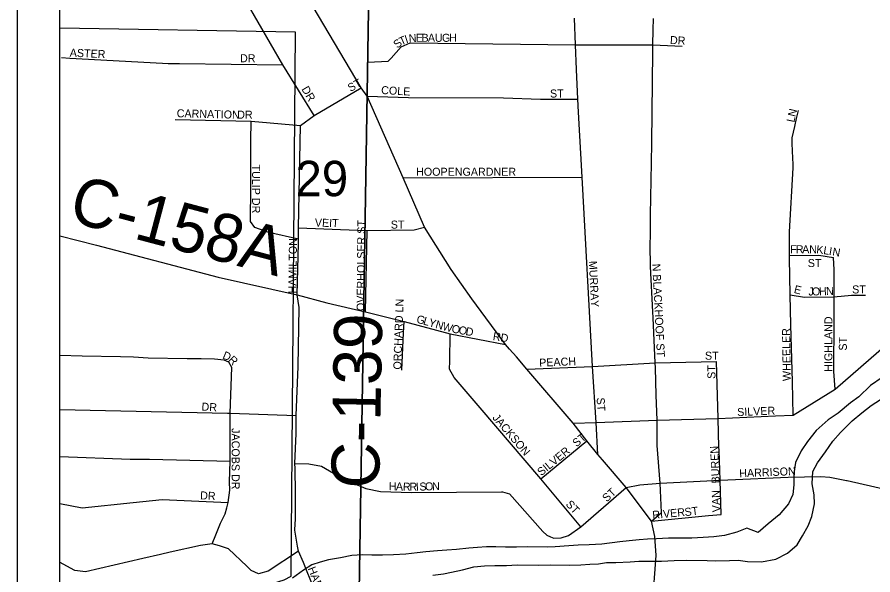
# Model space of a CAD drawing. Extents: x -784 to 1375, y -225 to 440.
# Drawn here: x 65.09 to 105.18, y 360.96 to 387.07 of the extents above; entities that cross this region are included whole.
import ezdxf

# ---------------------------------------------------------------- set-up
doc = ezdxf.new("R2010")
doc.units = 0
for name, color, linetype in [('GM_X_City_Street', 7, 'Continuous'), ('GM_X_City_Street_Text', 7, 'Continuous'), ('GM_X_County_Road', 7, 'Continuous'), ('GM_X_County_Road_Text', 7, 'Continuous'), ('GM_X_Major_River', 7, 'Continuous'), ('GM_X_Section', 7, 'Continuous'), ('GM_X_Section_Text', 7, 'Continuous'), ('GM_X_State_Route', 7, 'Continuous'), ('GM_X_Township_Subdivision', 7, 'Continuous'), ('GM_X_Township_Subdivision_Text', 7, 'Continuous'), ('SH_Data', 7, 'Continuous'), ('SH_Text', 7, 'Continuous')]:
    doc.layers.add(name, color=color, linetype=linetype)

msp = doc.modelspace()

# ---------------------------------------------------------------- linework, layer by layer
at = {"layer": 'GM_X_City_Street'}
for points in [[(78.997, 382.464), (77.542, 384.845), (75.795, 387.841), (74.481, 389.954), (73.204, 392.102)], [(91.299, 384.626), (91.251, 385.781), (91.193, 387.031)], [(94.867, 385.449), (94.871, 385.773), (94.887, 386.476), (94.895, 387.007)], [(82.604, 385.151), (83.079, 385.683), (83.496, 385.863), (91.251, 385.781), (94.871, 385.773), (96.249, 385.72)], [(94.762, 376.883), (94.764, 376.956), (94.756, 377.822), (94.813, 380.249), (94.821, 381.181), (94.867, 385.449)], [(67.166, 385.177), (67.561, 385.156), (71.899, 384.924), (72.172, 384.909), (72.688, 384.897), (77.542, 384.845)], [(81.51, 384.972), (82.474, 385.005), (82.604, 385.151)], [(91.391, 382.621), (91.357, 383.237), (91.299, 384.626)], [(78.263, 376.49), (78.268, 376.681), (78.276, 377.205), (78.366, 381.996), (78.997, 382.464), (81.206, 383.768)], [(81.494, 383.378), (83.422, 383.313), (87.876, 383.289), (89.603, 383.236), (89.623, 383.236), (91.357, 383.237)], [(92.295, 366.592), (92.218, 368.088), (92.035, 370.713), (91.561, 379.579), (91.391, 382.621)], [(101.271, 375.784), (101.269, 375.918), (101.277, 377.029), (101.444, 380.013), (101.439, 380.178), (101.416, 380.791), (101.402, 381.18), (101.393, 381.425), (101.515, 381.945), (101.603, 382.324), (101.692, 382.703)], [(72.489, 382.279), (76.053, 382.201), (78.366, 381.996)], [(78.268, 376.681), (76.884, 376.988), (76.22, 377.231), (76.015, 377.499), (76.015, 378.112), (76.041, 378.508), (76.041, 381.281), (76.053, 382.201)], [(83.168, 379.55), (91.561, 379.579)], [(81.035, 377.095), (81.483, 377.077), (83.693, 377.116), (84.172, 377.245)], [(78.276, 377.205), (81.035, 377.095)], [(81.407, 373.283), (81.483, 377.077)], [(94.877, 372.992), (94.862, 373.278), (94.764, 375.403), (94.748, 376.417), (94.762, 376.883)], [(78.2, 374.075), (78.263, 376.49)], [(101.269, 375.918), (102.65, 375.934), (103.328, 375.82)], [(101.44, 368.441), (101.408, 370.002), (101.334, 372.666), (101.301, 374.071), (101.271, 375.784)], [(103.41, 369.658), (103.353, 370.484), (103.369, 372.886), (103.369, 373.973), (103.361, 375.248), (103.328, 375.82)], [(101.301, 374.071), (101.98, 373.957), (103.369, 373.973), (103.506, 373.987)], [(103.506, 373.987), (103.688, 374.006), (104.17, 374.055), (104.832, 374.063)], [(81.407, 373.283), (83.221, 372.823), (85.38, 372.248), (87.965, 371.742)], [(94.99, 370.658), (94.985, 370.884), (94.877, 372.992)], [(83.112, 370.549), (83.183, 372.293), (83.221, 372.823)], [(91.136, 368.057), (92.218, 368.088), (95.074, 368.197), (97.931, 368.286), (100.615, 368.4), (101.44, 368.441), (103.41, 369.658), (107.019, 372.788)], [(86.782, 368.778), (85.565, 370.204), (85.348, 370.587), (85.353, 370.97), (85.38, 372.248)], [(88.97, 370.59), (92.035, 370.713), (94.985, 370.884), (97.853, 370.95)], [(97.969, 366.8), (97.963, 366.933), (97.931, 368.286), (97.853, 370.95)], [(94.813, 363.473), (95.271, 363.881), (95.207, 365.254), (95.075, 367.011), (95.074, 368.197), (95.017, 369.372), (94.99, 370.658)], [(91.496, 363.211), (89.622, 365.451), (86.782, 368.778)], [(89.622, 365.451), (91.773, 367.231)], [(98.074, 363.783), (98.025, 365.397), (97.969, 366.8)], [(78.102, 366.17), (78.75, 366.163), (79.34, 366.049), (80.388, 365.444), (81.431, 365.011), (82.118, 364.87), (83.565, 364.817), (87.78, 364.844)], [(93.612, 365.05), (94.258, 365.172), (95.207, 365.254), (98.025, 365.397), (98.38, 365.412)], [(98.38, 365.412), (101.212, 365.528), (102.74, 365.569), (103.165, 365.536), (103.944, 365.378)], [(103.944, 365.378), (103.973, 365.372), (106.368, 364.833), (107.061, 364.692)], [(87.78, 364.844), (87.82, 364.844), (88.152, 364.748), (89.718, 362.985), (89.903, 362.819), (90.08, 362.743)], [(90.08, 362.743), (90.229, 362.679), (90.58, 362.698), (90.912, 362.8), (91.496, 363.211), (93.612, 365.05)], [(94.813, 363.473), (97.469, 363.734), (98.074, 363.783)], [(80.763, 356.122), (80.35, 357.171), (79.837, 358.365), (79.646, 358.801), (79.202, 359.826), (78.949, 360.416), (78.674, 361.097), (78.505, 361.533), (78.268, 362.069), (78.228, 362.302)]]:
    msp.add_lwpolyline(points, dxfattribs=at)
at = {"layer": 'GM_X_County_Road'}
for points in [[(67.088, 376.839), (68.806, 376.391), (74.51, 374.895), (78.2, 374.075)], [(78.101, 363.077), (78.123, 363.584), (78.13, 364.273), (78.133, 364.808), (78.108, 365.934), (78.102, 366.17), (78.153, 367.579), (78.153, 368.421), (78.251, 370.723), (78.305, 373.484), (78.2, 374.075)], [(78.2, 374.075), (78.2, 374.075), (79.592, 373.704), (81.407, 373.283)], [(78.228, 362.302), (78.1, 363.048), (78.101, 363.077)]]:
    msp.add_lwpolyline(points, dxfattribs=at)
at = {"layer": 'GM_X_Major_River'}
for points in [[(105.617, 370.205), (105.071, 369.822), (104.524, 369.304), (104.129, 369.009), (103.552, 368.536), (103.082, 368.212), (102.52, 367.724), (102.107, 367.204), (101.816, 366.772), (101.553, 366.22), (101.471, 365.71), (101.479, 365.169), (101.428, 364.719), (101.227, 364.287), (100.785, 363.767), (100.268, 363.353), (99.797, 362.939), (99.274, 363.142), (98.806, 362.953), (98.218, 362.811), (97.722, 362.742), (97.225, 362.704), (96.699, 362.681), (96.128, 362.674), (95.603, 362.681), (95.046, 362.644), (94.626, 362.634), (94.235, 362.595), (93.753, 362.556), (93.317, 362.502), (92.474, 362.394), (91.888, 362.372), (91.377, 362.349), (90.926, 362.325), (90.295, 362.273), (89.919, 362.263), (89.003, 362.276), (88.477, 362.253), (87.966, 362.26), (87.515, 362.266), (87.08, 362.272), (86.659, 362.248), (86.253, 362.209), (85.666, 362.142), (85.215, 362.118), (84.779, 362.094), (84.238, 362.041), (83.831, 361.987), (83.29, 361.934)], [(84.569, 360.94), (85.065, 361.008), (85.442, 361.093), (85.954, 361.191), (86.482, 361.334), (86.978, 361.387), (87.474, 361.396), (88.015, 361.403), (88.511, 361.426), (89.502, 361.413), (90.058, 361.435), (90.974, 361.423), (91.5, 361.43), (91.921, 361.455), (92.327, 361.479), (92.703, 361.534), (93.139, 361.543), (93.8, 361.564), (94.206, 361.604), (94.837, 361.61), (95.273, 361.604), (95.874, 361.641), (96.43, 361.648), (97.421, 361.635), (97.797, 361.614), (98.458, 361.635), (98.864, 361.645), (99.299, 361.594), (99.959, 361.57), (100.637, 361.696), (101.181, 361.974), (101.637, 362.373), (101.883, 362.79), (102.145, 363.252), (102.316, 363.701), (102.444, 364.285), (102.419, 364.706), (102.336, 365.218), (102.359, 365.803), (102.575, 366.206), (102.957, 366.726), (103.294, 367.218), (103.66, 367.633), (104.208, 368.166), (104.664, 368.551), (105.089, 368.89), (105.528, 369.17)], [(83.29, 361.934), (82.719, 361.897), (82.208, 361.889), (81.712, 361.881), (81.262, 361.902), (80.765, 361.864), (80.238, 361.766), (79.681, 361.668), (79.289, 361.553), (78.897, 361.424), (78.503, 361.174), (77.987, 360.805)]]:
    msp.add_lwpolyline(points, dxfattribs=at)
at = {"layer": 'GM_X_Section'}
for points in [[(67.088, 397.216), (81.709, 397.114), (81.068, 357.283), (71.441, 357.464), (71.653, 357.594), (72.121, 357.736), (72.758, 358.099), (73.273, 358.374), (73.924, 358.677), (74.439, 358.982), (75.353, 359.701), (76.082, 360.182), (77.094, 360.568), (77.592, 360.724), (77.925, 360.897), (78.122, 386.365), (67.088, 386.554)], [(121.281, 389.014), (120.755, 357.05), (81.068, 357.283), (81.709, 397.114), (86.63, 397.087)]]:
    msp.add_lwpolyline(points, dxfattribs=at)
at = {"layer": 'GM_X_State_Route'}
for points in [[(81.494, 383.378), (81.206, 383.768), (73.671, 396.504), (73.39, 396.974)], [(81.494, 383.378), (81.51, 384.972), (81.682, 396.541), (81.683, 396.823)], [(88.155, 371.535), (87.965, 371.742), (86.396, 373.891), (85.424, 375.256), (84.172, 377.245), (83.168, 379.55), (81.494, 383.378)], [(92.503, 366.349), (92.295, 366.592), (91.773, 367.231), (91.136, 368.057), (88.97, 370.59), (88.488, 371.17), (88.155, 371.535)], [(94.853, 359.554), (95.026, 361.871), (94.969, 362.762), (94.813, 363.473), (93.612, 365.05), (92.503, 366.349)]]:
    msp.add_lwpolyline(points, dxfattribs=at)
at = {"layer": 'GM_X_Township_Subdivision'}
msp.add_line((67.088, 368.705), (74.937, 368.531), dxfattribs=at)
for points in [[(75.068, 368.528), (75.153, 370.671), (75, 370.916), (74.786, 371.008), (74.327, 371.061), (73.707, 371.077), (73.056, 371.077), (71.235, 371.1), (70.539, 371.146), (69.934, 371.168), (68.128, 371.207), (67.088, 371.238)], [(74.227, 362.413), (74.396, 362.842), (74.618, 363.385), (74.832, 363.814), (74.916, 364.097), (74.977, 364.357), (75.046, 364.924), (75.031, 365.322), (75.062, 366.278), (75.068, 368.528)], [(74.937, 368.531), (75.068, 368.528), (78.153, 368.421)], [(67.088, 366.498), (70.378, 366.385), (71.289, 366.378), (75.062, 366.278)], [(67.088, 364.3), (68.128, 364.097), (70.523, 364.342), (71.878, 364.495), (74.977, 364.357)], [(78.268, 362.069), (76.845, 361.135), (76.401, 361.013), (76.049, 361.166), (75.855, 361.375), (74.993, 362.176), (74.572, 362.322), (74.227, 362.413), (73.684, 362.329), (72.253, 362.031), (71.809, 361.916), (70.983, 361.732), (68.285, 361.109), (67.799, 361.158), (67.245, 361.466)], [(67.245, 361.466), (67.11, 361.541), (67.088, 361.548)]]:
    msp.add_lwpolyline(points, dxfattribs=at)
at = {"layer": 'SH_Data'}
msp.add_line((65.088, 421.485), (65.088, 281.485), dxfattribs=at)
at = {"layer": 'SH_Text'}
msp.add_lwpolyline([(67.088, 419.485), (203.088, 419.485), (203.088, 283.485), (67.088, 283.485)], close=True, dxfattribs=at)

# ---------------------------------------------------------------- texts
at = {"layer": 'GM_X_City_Street_Text'}
for s, rotation, p in [('T', 23.9125, (83.082, 385.744)), ('I', 17.8545, (83.313, 385.847)), ('N', 4.1339, (83.447, 385.893)), ('E', 0.2186, (83.77, 385.917)), ('B', 0, (84.033, 385.918)), ('A', 0, (84.33, 385.918)), ('U', 0, (84.66, 385.918)), ('G', 0, (84.99, 385.918)), ('H', 0, (85.32, 385.918)), ('DR', 356.8222, (95.664, 385.818)), ('S', 38.5318, (82.897, 385.592)), ('ASTER', 357.4519, (67.548, 385.225)), ('DR', 0, (75.53, 384.96)), ('ST', 29.755, (80.709, 383.565)), ('DR', 300.4734, (78.396, 383.705)), ('COLE', 356.8219, (82.134, 383.475)), ('ST', 0, (90.05, 383.31)), ('CARNATION', 358.6036, (72.562, 382.387)), ('DR', 0, (75.398, 382.32)), ('N', 76.409, (101.547, 382.382)), ('L', 79.033, (101.497, 382.127)), ('TULIP DR', 270, (76.096, 380.171)), ('HOOPENGARDNER', 0, (83.78, 379.647)), ('VEIT', 358.2112, (79.031, 377.271)), ('OVERHOLSER ST', 89.4887, (81.367, 373.308)), ('ST', 0, (82.592, 377.173)), ('HAMILTON', 89.2262, (78.166, 374.133)), ('F', 359.918, (101.303, 376.018)), ('R', 359.9466, (101.568, 376.017)), ('A', 359.9126, (101.864, 376.017)), ('N', 359.9363, (102.195, 376.016)), ('K', 354.5721, (102.515, 376.017)), ('L', 350.4748, (102.837, 375.986)), ('I', 350.2072, (103.097, 375.943)), ('N', 350.2289, (103.26, 375.915)), ('MURRAY', 272.8176, (91.87, 375.653)), ('ST', 0, (102.128, 375.372)), ('N BLACKHOOF ST', 272.9113, (94.84, 375.52)), ('E', 345.9702, (101.452, 374.167)), ('O', 1.3332, (102.325, 374.041)), ('H', 1.3562, (102.655, 374.049)), ('N', 1.3551, (102.985, 374.057)), ('ST', 0, (104.207, 374.137)), ('J', 1.3556, (102.16, 374.038)), ('ORCHARD LN', 88.0883, (83.083, 370.568)), ('G', 344.0816, (83.767, 372.781)), ('L', 344.1098, (84.084, 372.69)), ('Y', 344.0816, (84.338, 372.618)), ('N', 344.1022, (84.656, 372.527)), ('HIGHLAND', 90, (103.279, 370.469)), ('W', 344.8286, (84.978, 372.435)), ('O', 349.0222, (85.421, 372.316)), ('O', 349.694, (85.75, 372.253)), ('D', 349.694, (86.075, 372.194)), ('WHEELER', 90.8676, (101.332, 370.039)), ('RD', 351.0197, (87.355, 371.958)), ('ST', 90, (103.957, 371.459)), ('ST', 0, (97.31, 371.035)), ('PEACH', 2.4929, (89.552, 370.704)), ('ST', 90, (97.801, 370.139)), ('ST', 273.5746, (92.233, 369.252)), ('SILVER', 2.3405, (98.825, 368.394)), ('JACKSON', 310.5029, (87.332, 368.304)), ('ST', 39.7984, (91.292, 366.926)), ('SILVER', 39.2069, (89.643, 365.574)), ('BUREN', 92.4353, (97.999, 365.252)), ('HARRISON', 2.4182, (98.924, 365.524)), ('H', 358.2511, (82.496, 364.929)), ('A', 358.2363, (82.825, 364.919)), ('R', 358.3789, (83.156, 364.909)), ('R', 0.3027, (83.467, 364.901)), ('I', 1.3164, (83.771, 364.903)), ('S', 1.4377, (83.937, 364.906)), ('O', 1.4206, (84.201, 364.913)), ('N', 1.4355, (84.531, 364.921)), ('ST', 42.5022, (92.709, 364.35)), ('VAN', 91.9155, (98.032, 363.9)), ('ST', 312.5212, (90.762, 364.247)), ('RIVER', 5.4425, (94.862, 363.576)), ('ST', 7.1217, (96.378, 363.708)), ('HAMILTON ST', 291.6341, (78.696, 361.259))]:
    msp.add_text(s, height=0.375, rotation=rotation, dxfattribs=at).set_placement(p)
at = {"layer": 'GM_X_County_Road_Text'}
for s, rotation, p in [('C-158A', 345.1916, (67.426, 377.535)), ('C-139', 88.9103, (82.045, 364.985))]:
    msp.add_text(s, height=2.25, rotation=rotation, dxfattribs=at).set_placement(p)
at = {"layer": 'GM_X_Section_Text'}
msp.add_text('29', height=1.6575, rotation=0, dxfattribs=at).set_placement((78.129, 378.688))
at = {"layer": 'GM_X_Township_Subdivision_Text'}
for s, rotation, p in [('D', 337.9064, (74.684, 371.101)), ('R', 314.8111, (74.956, 370.998)), ('DR', 356.989, (73.719, 368.654)), ('JACOBS DR', 270, (75.139, 367.829)), ('DR', 356.989, (73.653, 364.5))]:
    msp.add_text(s, height=0.375, rotation=rotation, dxfattribs=at).set_placement(p)

doc.saveas('drawing.dxf')
